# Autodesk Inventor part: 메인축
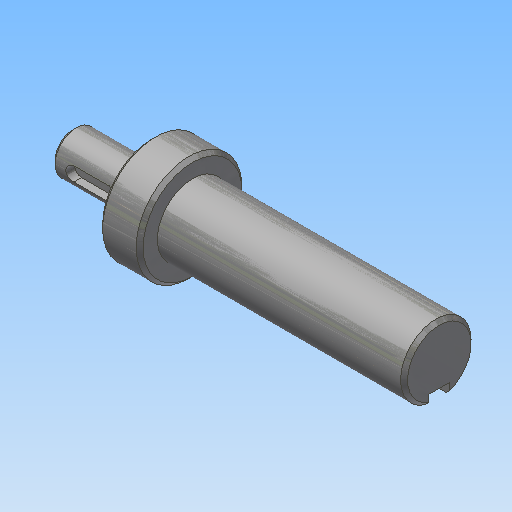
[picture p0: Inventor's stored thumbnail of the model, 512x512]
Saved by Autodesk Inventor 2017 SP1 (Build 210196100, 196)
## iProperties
Created: 2018-09
Part Number: 메인축
Document SubType Name: Modeling
Density: 7.86 g/cm^3
Material: 강철, 연강
Appearance: 강철
Mass: 251.954 g
Surface Area: 77.4403 cm^2
Volume: 32.0552 cm^3
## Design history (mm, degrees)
sketch "스케치1"
  geometry: L1 (34.997, -37.5)-(34.997, -77.5) reference; L2 (46.5, -38.401)-(46.5, -76.599) reference; L3 (12.497, -57.5)-(116.5, -57.5); L4 (12.497, -63.5)-(34.997, -63.5); L5 (34.997, -72.5)-(46.5, -72.5); L6 (46.5, -67.5)-(116.5, -67.5); L7 (116.5, -67.5)-(116.5, -57.5); L8 (12.497, -63.5)-(12.497, -57.5); 2 further points
  constraints: 12 end point, 5 point on line, 4 perpendicular, 1 midpoint, 1 parallel
  dimensions: "d0" = 20 diameter of L6 L3; "d1" = 30 diameter of L5 L3; "d2" = 22.5 distance of L4.start L4.end; "d3" = 70 distance of L6.start L6.end; "d5" = 12 diameter of L4 L3
revolve "회전1" sketch "스케치1" stored, may be unused: angle "d4" = 90 deg
chamfer "모따기1" distance "d6" = 1; stored, may be unused: second distance "d7" = 2, angle "d8" = 45 deg
node "작업 평면1"
sketch "스케치2"
  geometry: L1 (-11.25, -5)-(-11.25, 5) reference; L2 (-5.25, 2)-(4.75, 2); L3 (4.75, -2)-(-5.25, -2); A1 r 2 centre (4.75, 0) between (4.75, -2) and (4.75, 2); A2 r 2 centre (-5.25, 0) between (-5.25, 2) and (-5.25, -2); 2 further points
  constraints: 4 end point, 4 point on circle, 4 tangent, 2 centre point, 1 horizontal alignment, 1 midpoint, 1 parallel, 1 perpendicular
  dimensions: "d9" = 4 distance between parallel lines of L3 L2; "d10" = 14 dimension on A1 A2; "d11" = 4 distance edge to line of A2 L1
extrude "돌출1" cut sketch "스케치2" distance "d12" = 2.5; taper "d13" = 0 deg
node "작업 평면2"
sketch "스케치3"
  geometry: L1 (35, 9)-(35, -9) reference; L2 (35, 3)-(20, 3); L3 (20, -3)-(35, -3); A1 r 3 centre (20, 0) between (20, 3) and (20, -3); 2 further points
  constraints: 4 end point, 2 perpendicular, 2 point on circle, 2 point on line, 2 tangent, 1 centre point, 1 horizontal alignment, 1 midpoint
  dimensions: "d14" = 6 distance between parallel lines of L3 L2; "d15" = 18 dimension on A1 L1
extrude "돌출2" cut sketch "스케치3" distance "d16" = 3.5; taper "d17" = 0 deg
node "솔리드1"
node "참조1"
node "참조2"
